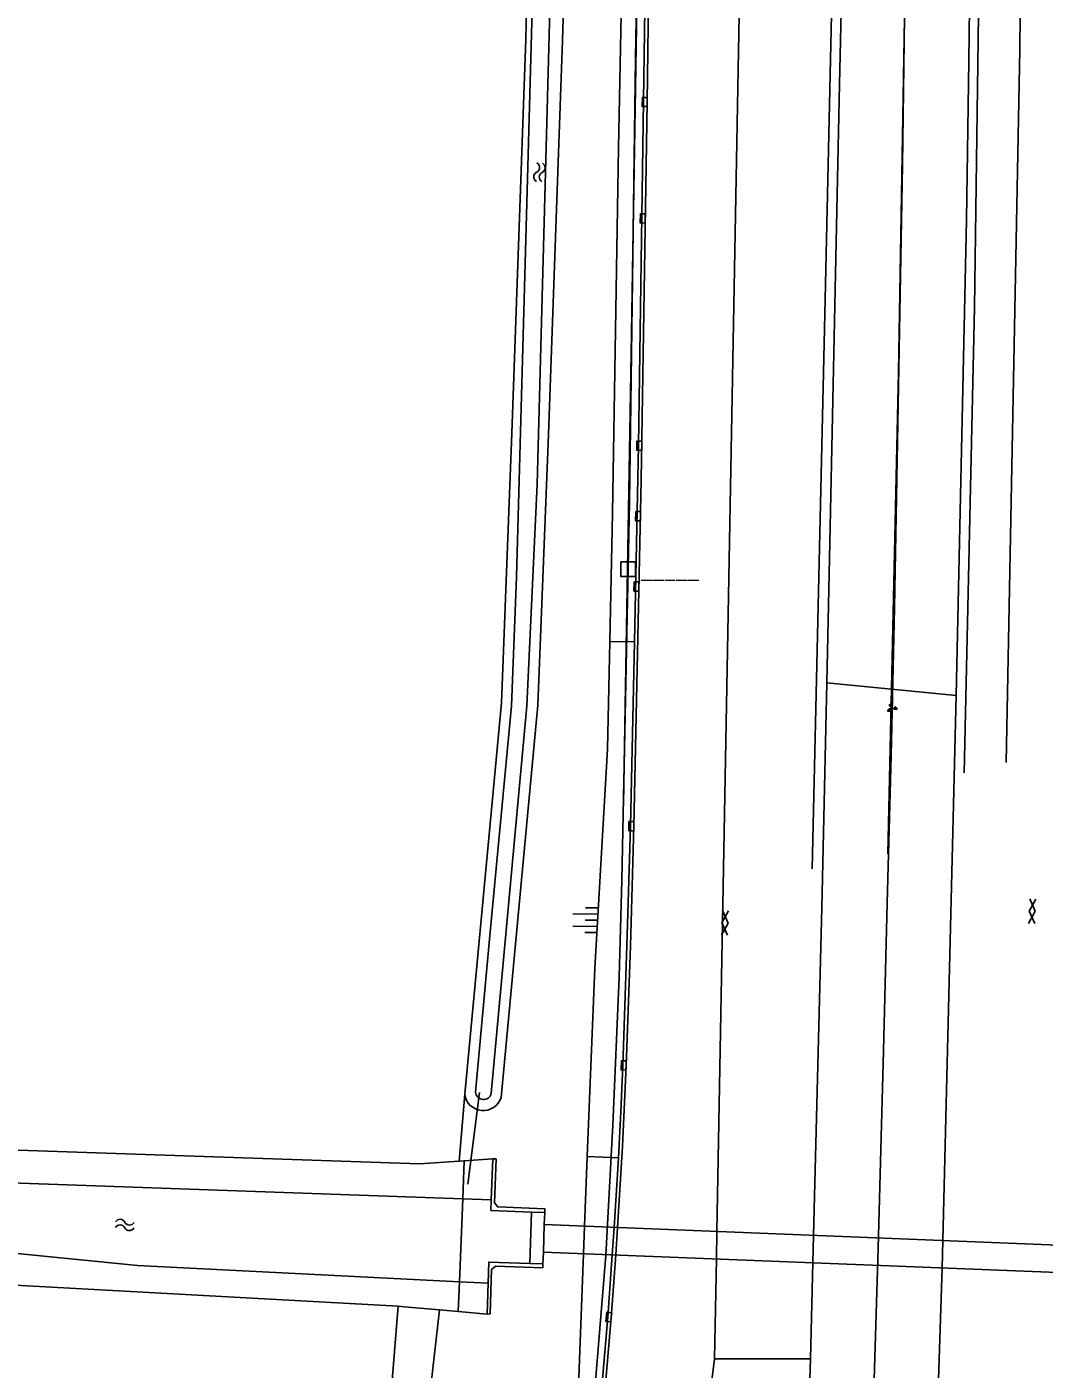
# Model space of a CAD drawing. Extents: x 133000 to 136000, y 400500 to 403500.
# Drawn here: x 133078.7 to 133161.4, y 401393.6 to 401502.7 of the extents above; entities that cross this region are included whole.
import ezdxf

# ---------------------------------------------------------------- set-up
doc = ezdxf.new("R2010")
doc.units = 0
for name, color, linetype in [('gg-knt-bovenkant onderkant talud', 7, 'Continuous'), ('gg-knt-verharding', 7, 'Continuous'), ('gg-kwrk-duiker nz buis', 7, 'Continuous'), ('gg-kwrk-duiker nz vlak', 7, 'Continuous'), ('gg-kwrk-kunstwerk', 7, 'Continuous'), ('gg-kwrk-stuw', 7, 'Continuous'), ('gt-grn-groengrens', 7, 'Continuous'), ('gt-knt-geleideconstructie', 7, 'Continuous'), ('gt-symb-gesloten verharding', 7, 'Continuous'), ('gt-symb-groenvak', 7, 'Continuous'), ('gt-symb-hm paal', 7, 'Continuous'), ('gt-symb-kolk', 7, 'Continuous'), ('gt-symb-talud symbool', 7, 'Continuous'), ('gt-symb-watersymbool', 7, 'Continuous'), ('gx-grn-maaiveld', 7, 'Continuous'), ('gx-knt-lijn weginrichtingselement', 7, 'Continuous')]:
    doc.layers.add(name, color=color, linetype=linetype)

# ---------------------------------------------------------------- blocks, each defined once
blk = doc.blocks.new('gt0-WA')
at = {"layer": 'gt-symb-watersymbool'}
for centre, start, end in [((-0.32, 0.02), 28.0725, 151.9275), ((0.43, 0.42), 208.0725, 331.9275), ((-0.32, -0.43), 28.0725, 151.9275), ((0.43, -0.03), 208.0725, 331.9275)]:
    blk.add_arc(centre, 0.425, start, end, dxfattribs=at)
blk = doc.blocks.new('gt0-TALUD_1')
at = {"layer": 'gt-symb-talud symbool'}
for p, q in [((-1, -1), (-1, 0)), ((0.5, -2), (0.5, 0)), ((-0.5, -2), (-0.5, 0)), ((0, -1), (0, 0)), ((1, -1), (1, 0))]:
    blk.add_line(p, q, dxfattribs=at)
blk = doc.blocks.new('gt0-GESVH1')
at = {"layer": 'gt-symb-gesloten verharding'}
for p, q in [((-0.99, -0.26), (0.01, 0.24)), ((0.01, -0.26), (-0.99, 0.24)), ((0.01, 0.24), (1.01, -0.26)), ((1.01, 0.24), (0.01, -0.26))]:
    blk.add_line(p, q, dxfattribs=at)
blk = doc.blocks.new('gt0-KOLK')
at = {"layer": 'gt-symb-kolk'}
blk.add_lwpolyline([(0, 0), (0.38, 0), (0.38, 0.4), (-0.37, 0.4), (-0.37, 0), (0, 0)], dxfattribs=at)
blk = doc.blocks.new('gt0-GRVAK')
at = {"layer": 'gt-symb-groenvak'}
for p, q in [((-0.11, 0.19), (-0.23, 0.24)), ((-0.18, 0.15), (0.09, 0.15)), ((-0.09, 0.21), (-0.16, 0.32)), ((-0.05, 0.21), (-0.05, 0.39)), ((0, 0.21), (0.06, 0.32)), ((0.01, 0.19), (0.13, 0.24)), ((0.26, -0.05), (0.2, 0.06)), ((0.3, -0.05), (0.3, 0.13)), ((0.35, -0.05), (0.41, 0.06)), ((-0.25, -0.23), (-0.36, -0.18)), ((-0.32, -0.26), (-0.05, -0.26)), ((-0.23, -0.21), (-0.29, -0.1)), ((-0.18, -0.2), (-0.18, -0.02)), ((-0.14, -0.21), (-0.07, -0.1)), ((-0.12, -0.23), (0, -0.18)), ((0.24, -0.07), (0.12, -0.02)), ((0.17, -0.11), (0.44, -0.11)), ((0.37, -0.07), (0.49, -0.02))]:
    blk.add_line(p, q, dxfattribs=at)
blk = doc.blocks.new('gt0-HMpaal')
at = {"layer": 'gt-symb-hm paal'}
blk.add_lwpolyline([(-0.6, 0.6), (0.6, 0.6), (0.6, -0.6), (-0.6, -0.6)], close=True, dxfattribs=at)

msp = doc.modelspace()

# ---------------------------------------------------------------- linework, layer by layer
at = {"layer": 'gg-knt-bovenkant onderkant talud'}
for p, q in [((133124.24, 401410.9), (133124.02, 401405.24)), ((133124.02, 401405.24), (133123.94, 401403.01))]:
    msp.add_line(p, q, dxfattribs=at)
for points in [[(133126.08, 401452.78), (133125.89, 401444.03), (133124.87, 401426.21), (133124.24, 401410.9)], [(133123.94, 401403.01), (133123.45, 401390.07), (133121.94, 401372.85), (133119.94, 401355.67), (133116.67, 401335.59), (133113.16, 401316.85), (133109.61, 401299.43), (133105.58, 401282.95)]]:
    msp.add_lwpolyline(points, dxfattribs=at)
at = {"layer": 'gg-knt-verharding'}
for p, q in [((133134.78, 401404.81), (133138.47, 401606.08)), ((133153.14, 401404.07), (133154.24, 401448.39)), ((133126.43, 401405.14), (133126.78, 401410.79)), ((133126.28, 401402.92), (133126.43, 401405.14)), ((133126.57, 401402.91), (133126.72, 401405.13)), ((133134.74, 401402.59), (133134.78, 401404.81)), ((133142.63, 401404.49), (133142.57, 401402.28)), ((133153.08, 401401.86), (133153.14, 401404.07)), ((133134.59, 401394.46), (133134.74, 401402.59)), ((133142.57, 401402.28), (133142.38, 401394.46)), ((133151.32, 401347.88), (133153.08, 401401.86)), ((133134.59, 401394.46), (133129.05, 401351.05)), ((133142.38, 401394.46), (133134.59, 401394.46))]:
    msp.add_line(p, q, dxfattribs=at)
for points in [[(133131.41, 401606.33), (133131.19, 401597.33), (133130.48, 401566.43), (133130.28, 401556.95), (133129.57, 401527.53), (133129.24, 401507.07), (133129.12, 401496.62), (133128.62, 401465.91), (133128.03, 401437.75), (133127.75, 401428.02), (133127.41, 401418.3), (133127.1, 401411.71), (133126.72, 401405.13)], [(133131.16, 401606.34), (133129.31, 401527.51), (133129.13, 401517.3), (133128.41, 401468.7), (133128.08, 401452.75)], [(133147.07, 401605.77), (133146.48, 401578.85), (133145.66, 401538.27), (133144.76, 401498.09), (133144, 401462.1), (133143.72, 401449.41)], [(133154.24, 401448.39), (133155.08, 401487.04), (133155.25, 401500)], [(133128.08, 401452.75), (133127.77, 401437.77), (133127.47, 401428.04), (133127.13, 401418.31), (133126.97, 401414.55), (133126.78, 401410.79)], [(133143.72, 401449.41), (133143.3, 401431.13), (133142.63, 401404.49)], [(133120.41, 401348.76), (133121.89, 401359.36), (133123.13, 401369.05), (133123.76, 401374.3), (133124.14, 401377.67), (133124.7, 401383.61), (133125.92, 401397.85), (133126.28, 401402.92)], [(133125.55, 401390.19), (133126.2, 401397.83), (133126.57, 401402.91)], [(133142.38, 401394.46), (133141.48, 401366.36), (133140.55, 401339.01), (133138.44, 401284.16), (133137.73, 401268.59)]]:
    msp.add_lwpolyline(points, dxfattribs=at)
at = {"layer": 'gg-kwrk-duiker nz buis'}
msp.add_line((133114.54, 401408.65), (133115.48, 401416.12), dxfattribs=at)
at = {"layer": 'gg-kwrk-duiker nz vlak'}
for p, q in [((133176.3, 401403.14), (133120.75, 401405.37)), ((133176.22, 401400.95), (133120.68, 401403.14))]:
    msp.add_line(p, q, dxfattribs=at)
at = {"layer": 'gg-kwrk-kunstwerk'}
for p, q in [((133116.45, 401407.4), (133116.58, 401410.73)), ((133116.2, 401400.61), (133116.12, 401398.1))]:
    msp.add_line(p, q, dxfattribs=at)
for points in [[(133116.58, 401410.73), (133116.84, 401410.71), (133116.7, 401407.14), (133116.98, 401406.81), (133120.8, 401406.66), (133120.79, 401406.35)], [(133116.45, 401407.4), (133116.42, 401406.52), (133119.73, 401406.39)], [(133116.12, 401398.1), (133116.35, 401398.11), (133116.48, 401401.72), (133116.79, 401401.99), (133120.63, 401401.87), (133120.64, 401402.19)], [(133119.57, 401402.22), (133116.25, 401402.32), (133116.2, 401400.61)]]:
    msp.add_lwpolyline(points, dxfattribs=at)
at = {"layer": 'gg-kwrk-stuw'}
for p, q in [((133119.73, 401406.39), (133119.57, 401402.22)), ((133119.73, 401406.39), (133120.79, 401406.35)), ((133120.75, 401405.37), (133120.68, 401403.14)), ((133120.79, 401406.35), (133120.75, 401405.37)), ((133120.68, 401403.14), (133120.64, 401402.19)), ((133119.57, 401402.22), (133120.64, 401402.19))]:
    msp.add_line(p, q, dxfattribs=at)
at = {"layer": 'gt-grn-groengrens'}
for p, q in [((133126.08, 401452.78), (133128.08, 401452.75)), ((133148.97, 401448.9), (133143.72, 401449.41)), ((133154.24, 401448.39), (133148.97, 401448.9)), ((133124.24, 401410.9), (133126.78, 401410.79))]:
    msp.add_line(p, q, dxfattribs=at)
at = {"layer": 'gt-knt-geleideconstructie'}
for points in [[(133131.52, 401639.81), (133130.58, 401601.1), (133129.66, 401569.46), (133128.84, 401534.78), (133128.47, 401518.78), (133128.31, 401508.18), (133128.16, 401500.17), (133127.9, 401480.14), (133127.67, 401464.09), (133127.06, 401433.38), (133126.83, 401425.5), (133126.34, 401413.46), (133125.76, 401402.85), (133125.1, 401394.94), (133124.56, 401388.33)], [(133148.95, 401443.48), (133149.22, 401455.51), (133149.42, 401467.51), (133149.64, 401479.51), (133149.87, 401491.5), (133150.03, 401503.51), (133150.22, 401515.54), (133150.36, 401527.52), (133150.45, 401538.25)], [(133145.68, 401335.43), (133146.1, 401347.37), (133146.53, 401359.43), (133147.05, 401375.42), (133147.41, 401387.45), (133147.88, 401403.46), (133148.33, 401419.49), (133148.61, 401431.49), (133148.95, 401443.48)]]:
    msp.add_lwpolyline(points, dxfattribs=at)
at = {"layer": 'gx-grn-maaiveld'}
for p, q in [((133113.83, 401410.54), (133114.29, 401415.97)), ((133114.25, 401410.57), (133113.83, 401410.54)), ((133114.25, 401410.57), (133114.13, 401407.48)), ((133116.58, 401410.73), (133114.25, 401410.57)), ((133114.13, 401407.48), (133113.86, 401400.72)), ((133114.13, 401407.48), (133116.45, 401407.4)), ((133108.87, 401398.73), (133061.14, 401401.37)), ((133113.77, 401398.31), (133113.86, 401400.72)), ((133113.86, 401400.72), (133116.2, 401400.61)), ((133112.25, 401398.45), (133111.56, 401392.48)), ((133112.25, 401398.45), (133113.77, 401398.31)), ((133113.77, 401398.31), (133116.12, 401398.1))]:
    msp.add_line(p, q, dxfattribs=at)
for points in [[(133155.32, 401731.7), (133155.79, 401688.86), (133156.03, 401637.82), (133155.81, 401567.36), (133155.58, 401525.69), (133155.25, 401500)], [(133130.01, 401606.38), (133129.97, 401604.46), (133129.45, 401601.39), (133128.84, 401584.3), (133127.9, 401552.1), (133127.35, 401521.39), (133126.8, 401492.94), (133126.31, 401463.2), (133126.08, 401452.78)], [(133115.18, 401416.15), (133116.3, 401428.58), (133118.1, 401447.55), (133118.51, 401458.03), (133120.46, 401528.67), (133123.61, 401592.05), (133123.73, 401603.04), (133124.83, 401603.04), (133124.69, 401592.05), (133121.68, 401521.38), (133120.17, 401465.56), (133119.33, 401447.54), (133116.45, 401416.02)], [(133125.64, 401603.61), (133125.57, 401591.79), (133124.49, 401565.74), (133122.97, 401525.82), (133122.23, 401501.64), (133121.1, 401469.59), (133120.24, 401447.6), (133117.25, 401415.7)], [(133114.29, 401415.97), (133117.27, 401447.8), (133118.12, 401469.7), (133119.25, 401501.74), (133119.69, 401522.57), (133120.46, 401549.12), (133121.28, 401564.7)], [(133075.59, 401411.51), (133110.62, 401410.31), (133113.83, 401410.54)], [(133114.13, 401407.48), (133075.83, 401408.82), (133073.23, 401409.58), (133071.76, 401410.41)], [(133113.86, 401400.72), (133087.71, 401402.04), (133060.51, 401404.76), (133060.51, 401405.38)], [(133079.99, 401285.47), (133094.71, 401318.67), (133102.23, 401346.19), (133105.51, 401363.02), (133107.09, 401376.67), (133108.87, 401398.73)], [(133112.25, 401398.45), (133109.37, 401398.7), (133108.87, 401398.73)]]:
    msp.add_lwpolyline(points, dxfattribs=at)
for centre, radius, start, end in [((133115.8, 401416.16), 1.52, 187.1487, 342.3821), ((133115.82, 401416.19), 0.646, 183.5732, 345.1843)]:
    msp.add_arc(centre, radius, start, end, dxfattribs=at)
at = {"layer": 'gx-knt-lijn weginrichtingselement'}
for points in [[(133154.88, 401442.09), (133155.73, 401479.91), (133156.3, 401523.56), (133156.59, 401560.96), (133156.8, 401601.27), (133156.75, 401636.03), (133156.51, 401678.76), (133156.02, 401731.73)], [(133159.46, 401731.89), (133160.08, 401670.74), (133160.27, 401611.21), (133159.99, 401562.66), (133159.39, 401500.92), (133158.29, 401442.93)], [(133131.97, 401730.5), (133132.02, 401718), (133132.16, 401704.62), (133132.26, 401682.85), (133132, 401668.75), (133131.5, 401643.89), (133130.94, 401625.21), (133130.61, 401608.93), (133129.5, 401567.99), (133128.52, 401519.43), (133127.81, 401476.18), (133127.19, 401439.54)], [(133144.22, 401731.19), (133144.3, 401709.25), (133145.42, 401689.13), (133146.22, 401674.29), (133147.18, 401654.28), (133147.23, 401647.59), (133147.01, 401641.07), (133146.72, 401626.51), (133146.3, 401608.71), (133145.58, 401576.14), (133144.71, 401531.76), (133143.56, 401479.39), (133142.53, 401434.3)], [(133148.67, 401435.5), (133149.55, 401474.7), (133150.35, 401522.63), (133150.53, 401540.13)]]:
    msp.add_lwpolyline(points, dxfattribs=at)

# ---------------------------------------------------------------- block references
at = {"layer": 'gt-symb-gesloten verharding'}
for p, rotation in [((133160.42, 401430.86), -92.46466335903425), ((133135.45, 401429.91), -92.46466335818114)]:
    msp.add_blockref('gt0-GESVH1', p, dxfattribs=dict(at, rotation=rotation))
at = {"layer": 'gt-symb-groenvak'}
msp.add_blockref('gt0-GRVAK', (133148.98, 401447.37), dxfattribs=at)
at = {"layer": 'gt-symb-hm paal'}
msp.add_blockref('gt0-HMpaal', (133127.57, 401458.66), dxfattribs=at)
at = {"layer": 'gt-symb-kolk'}
for p, rotation in [((133129.12, 401496.62), 89.32216606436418), ((133128.96, 401487.16), 89.05578259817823), ((133128.68, 401468.68), 89.18488754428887), ((133128.58, 401462.95), 88.99123363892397), ((133128.45, 401457.23), 88.74902302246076), ((133128.03, 401437.75), 88.77322800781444), ((133127.41, 401418.3), 88.01449840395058), ((133126.2, 401397.83), 84.8852043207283)]:
    msp.add_blockref('gt0-KOLK', p, dxfattribs=dict(at, rotation=rotation))
at = {"layer": 'gt-symb-talud symbool', "xscale": 1.0001124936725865, "yscale": 1.000112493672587, "rotation": -90.85937224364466}
msp.add_blockref('gt0-TALUD_1', (133125.08, 401430.11), dxfattribs=at)
at = {"layer": 'gt-symb-watersymbool'}
for p, rotation in [((133120.37, 401490.97), -92.00653893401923), ((133086.61, 401405.35), -1.4320961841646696)]:
    msp.add_blockref('gt0-WA', p, dxfattribs=dict(at, rotation=rotation))

# ---------------------------------------------------------------- texts
at = {"layer": 'gt-symb-hm paal'}
msp.add_text('_____', height=1.25, dxfattribs=at).set_placement((133128.65, 401458.05))

doc.saveas('drawing.dxf')
